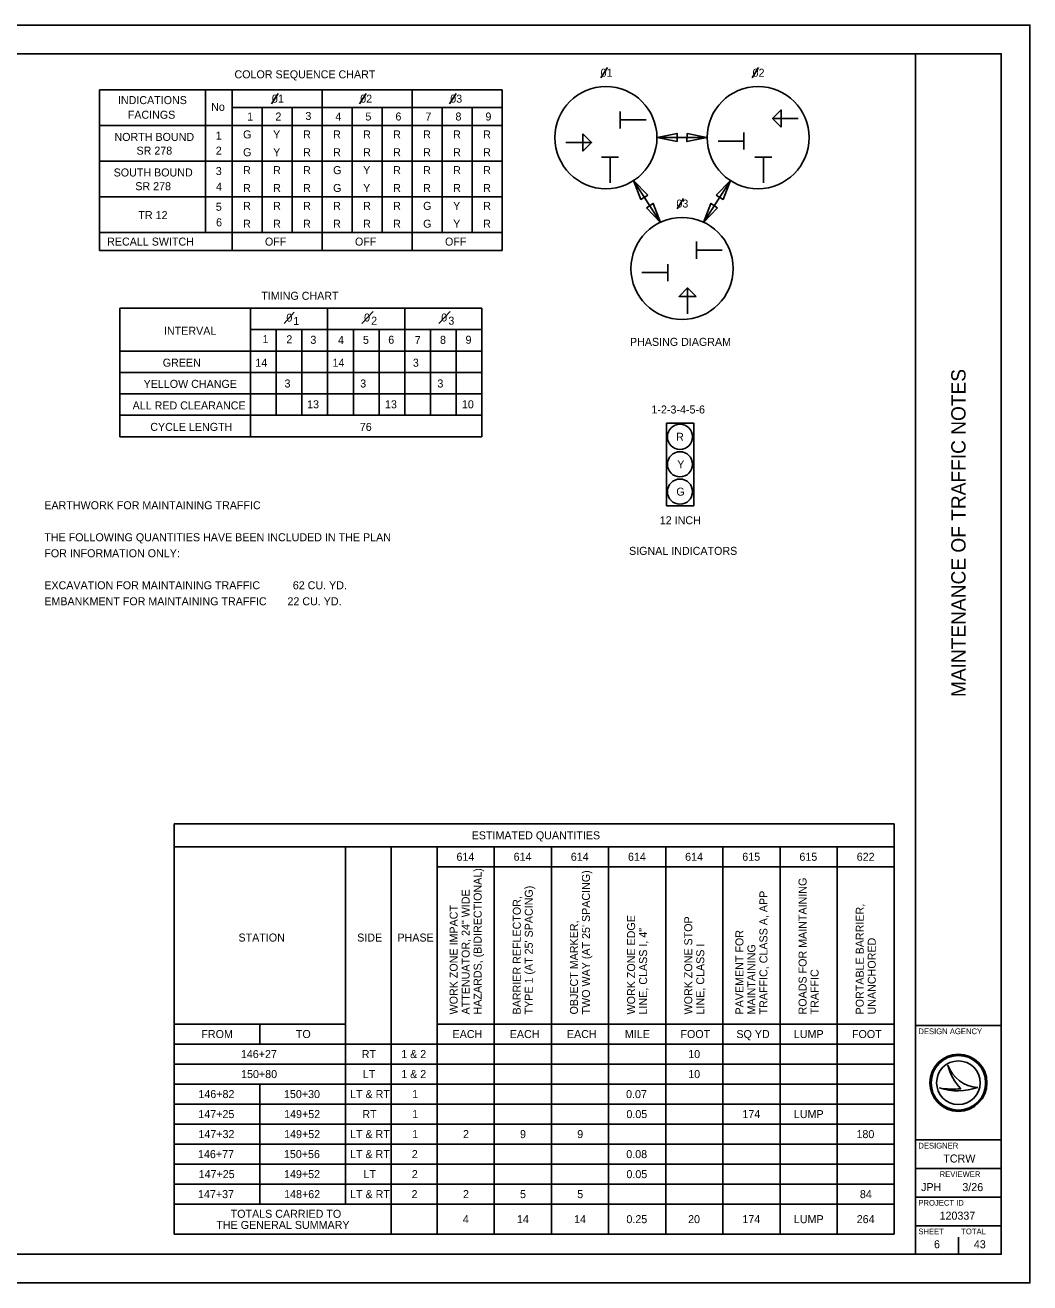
# Model space of a CAD drawing. Extents: x -39 to 34, y 0 to 22.
# Drawn here: x 16.42 to 34, y 0 to 22 of the extents above; entities that cross this region are included whole.
import ezdxf

# ---------------------------------------------------------------- set-up
doc = ezdxf.new("R2010")
doc.units = 0
for name, color, linetype in [('Default', 7, 'Continuous'), ('SG_P_Heads', 7, 'Continuous'), ('SH_Border', 7, 'Continuous'), ('SH_Cut_Line', 7, 'Continuous'), ('SH_Data', 7, 'Continuous'), ('SH_Text', 7, 'Continuous'), ('TX_P_1', 7, 'Continuous'), ('TX_P_20', 7, 'Continuous')]:
    doc.layers.add(name, color=color, linetype=linetype)

msp = doc.modelspace()

# ---------------------------------------------------------------- linework, layer by layer
at = {"layer": 'Default'}
for p, q in [((17.725, 20.871), (17.725, 18.059)), ((17.725, 20.871), (24.77, 20.871)), ((19.576, 20.871), (19.576, 18.371)), ((20.045, 20.871), (20.045, 18.059)), ((21.62, 20.871), (21.62, 18.059)), ((23.195, 20.871), (23.195, 18.684)), ((23.195, 20.871), (23.195, 18.059)), ((24.77, 20.871), (24.77, 18.059)), ((20.045, 20.559), (24.77, 20.559)), ((20.57, 20.559), (20.57, 18.371)), ((21.095, 20.559), (21.095, 18.371)), ((22.145, 20.559), (22.145, 18.371)), ((22.67, 20.559), (22.67, 18.371)), ((23.72, 20.559), (23.72, 18.371)), ((24.245, 20.559), (24.245, 18.371)), ((17.725, 20.246), (24.77, 20.246)), ((17.725, 19.621), (24.77, 19.621)), ((17.725, 18.996), (24.77, 18.996)), ((17.725, 18.371), (24.77, 18.371)), ((17.725, 18.059), (24.77, 18.059)), ((18.08, 17.05), (24.415, 17.05)), ((18.08, 17.05), (18.08, 14.8)), ((20.365, 17.05), (20.365, 14.8)), ((21.715, 17.05), (21.715, 15.175)), ((23.065, 17.05), (23.065, 15.175)), ((24.415, 17.05), (24.415, 14.8)), ((20.365, 16.675), (24.415, 16.675)), ((20.815, 16.675), (20.815, 15.175)), ((21.265, 16.675), (21.265, 15.175)), ((22.165, 16.675), (22.165, 15.175)), ((22.615, 16.675), (22.615, 15.175)), ((23.515, 16.675), (23.515, 15.175)), ((23.965, 16.675), (23.965, 15.175)), ((18.08, 16.3), (24.415, 16.3)), ((18.08, 15.925), (24.415, 15.925)), ((18.08, 15.55), (24.415, 15.55)), ((18.08, 15.175), (24.415, 15.175)), ((28.119, 15.036), (27.641, 15.036)), ((27.641, 15.036), (27.641, 13.594)), ((28.119, 13.594), (28.119, 15.036)), ((18.08, 14.8), (24.415, 14.8)), ((27.641, 13.594), (28.119, 13.594))]:
    msp.add_line(p, q, dxfattribs=at)
for centre in [(27.879, 14.799), (27.879, 14.319), (27.879, 13.84)]:
    msp.add_circle(centre, 0.22, dxfattribs=at)
at = {"layer": 'SG_P_Heads'}
for p, q in [((26.834, 20.491), (26.834, 20.191)), ((27.285, 20.341), (26.834, 20.341)), ((29.949, 20.367), (29.498, 20.367)), ((28.996, 19.823), (28.996, 20.123)), ((25.882, 19.947), (26.332, 19.947)), ((28.545, 19.973), (28.996, 19.973)), ((26.505, 19.693), (26.805, 19.693)), ((26.655, 19.242), (26.655, 19.693)), ((29.188, 19.693), (29.488, 19.693)), ((29.338, 19.242), (29.338, 19.693)), ((28.166, 18.215), (28.166, 17.915)), ((28.617, 18.065), (28.166, 18.065)), ((27.664, 17.521), (27.664, 17.821)), ((27.214, 17.671), (27.664, 17.671)), ((28.013, 16.953), (28.013, 17.404))]:
    msp.add_line(p, q, dxfattribs=at)
for points in [[(29.648, 20.217), (29.498, 20.367), (29.648, 20.517)], [(26.182, 20.097), (26.332, 19.947), (26.182, 19.797)], [(27.828, 19.965), (27.478, 20.037), (27.828, 20.105)], [(28.002, 20.104), (28.351, 20.032), (28.001, 19.964)], [(27.314, 19.027), (27.064, 19.282), (27.197, 18.951)], [(28.515, 19.027), (28.765, 19.282), (28.633, 18.951)], [(27.291, 18.805), (27.541, 18.55), (27.409, 18.882)], [(28.538, 18.805), (28.288, 18.55), (28.421, 18.882)], [(28.163, 17.254), (28.013, 17.404), (27.863, 17.254)]]:
    msp.add_lwpolyline(points, close=True, dxfattribs=at)
at = {"layer": 'SH_Border'}
for p, q in [((32, 0.5), (32, 21.5)), ((32, 4.5), (33.5, 4.5)), ((32, 2.5), (33.5, 2.5)), ((32, 2), (33.5, 2)), ((32, 1.5), (33.5, 1.5)), ((32, 1), (33.5, 1))]:
    msp.add_line(p, q, dxfattribs=at)
msp.add_lwpolyline([(1.5, 21.5), (33.5, 21.5), (33.5, 0.5), (1.5, 0.5)], close=True, dxfattribs=at)
at = {"layer": 'SH_Cut_Line'}
msp.add_lwpolyline([(0, 0), (34, 0), (34, 22), (0, 22)], close=True, dxfattribs=at)
at = {"layer": 'SH_Data'}
for p, q in [((28.351, 20.032), (27.478, 20.037)), ((27.541, 18.55), (27.064, 19.282)), ((28.288, 18.55), (28.765, 19.282)), ((32.567, 3.81), (32.567, 3.81)), ((32.417, 3.41), (32.417, 3.41)), ((32.75, 3.5), (32.75, 3.5)), ((33.087, 3.419), (33.087, 3.419)), ((32.375, 0.675), (32.375, 0.675)), ((32.75, 0.5), (32.75, 0.8))]:
    msp.add_line(p, q, dxfattribs=at)
for centre, radius in [((26.583, 20.032), 0.893), ((29.246, 20.032), 0.893), ((27.915, 17.743), 0.893), ((32.75, 3.5), 0.5), ((32.75, 3.5), 0.477), ((32.75, 3.5), 0.477), ((32.75, 3.5), 0.382)]:
    msp.add_circle(centre, radius, dxfattribs=at)
for centre, radius, start, end in [((33.116, 3.998), 0.58, 198.9257, 198.9319), ((33.347, 3.97), 0.796, 191.6379, 191.6421), ((33.116, 3.998), 0.58, 198.9319, 267.1657), ((33.347, 3.97), 0.796, 191.6421, 226.0947), ((32.739, 4.37), 1.013, 251.4576, 290.0832), ((32.648, 4.654), 1.266, 259.4964, 259.4995), ((32.739, 4.37), 1.013, 251.4527, 251.4576), ((32.648, 4.654), 1.266, 259.4995, 276.6672)]:
    msp.add_arc(centre, radius, start, end, dxfattribs=at)
at = {"layer": 'SH_Text'}
for p, q in [((19.029, 0.852), (19.029, 8.028)), ((19.029, 8.028), (31.629, 8.028)), ((31.629, 0.852), (31.629, 8.028)), ((19.029, 7.628), (31.629, 7.628)), ((22.029, 1.377), (22.029, 7.628)), ((22.829, 0.852), (22.829, 7.628)), ((23.629, 0.852), (23.629, 7.628)), ((24.629, 0.852), (24.629, 7.628)), ((25.629, 0.852), (25.629, 7.628)), ((26.629, 0.852), (26.629, 7.628)), ((27.629, 0.852), (27.629, 7.628)), ((28.629, 0.852), (28.629, 7.628)), ((29.629, 0.852), (29.629, 7.628)), ((30.629, 0.852), (30.629, 7.628)), ((23.629, 7.278), (31.629, 7.278)), ((19.029, 4.527), (22.029, 4.527)), ((20.529, 4.177), (20.529, 4.527)), ((23.629, 4.527), (31.629, 4.527)), ((19.029, 4.177), (31.629, 4.177)), ((19.029, 3.827), (31.629, 3.827)), ((19.029, 3.477), (31.629, 3.477)), ((20.529, 1.377), (20.529, 3.477)), ((19.029, 3.127), (31.629, 3.127)), ((19.029, 2.777), (31.629, 2.777)), ((19.029, 2.427), (31.629, 2.427)), ((19.029, 2.077), (31.629, 2.077)), ((19.029, 1.727), (31.629, 1.727)), ((19.029, 1.377), (31.629, 1.377)), ((19.029, 0.852), (31.629, 0.852))]:
    msp.add_line(p, q, dxfattribs=at)
at = {"layer": 'TX_P_1'}
for p, q in [((26.496, 21.077), (26.611, 21.258)), ((29.14, 21.077), (29.255, 21.258)), ((20.735, 20.624), (20.85, 20.805)), ((22.273, 20.624), (22.388, 20.805)), ((23.848, 20.624), (23.963, 20.805)), ((27.828, 18.788), (27.943, 18.969)), ((20.955, 16.781), (21.131, 16.981)), ((22.311, 16.782), (22.511, 16.991)), ((23.661, 16.782), (23.861, 16.991))]:
    msp.add_line(p, q, dxfattribs=at)

# ---------------------------------------------------------------- texts
at = {"layer": 'Default'}
for s, p in [('R', (27.811, 14.729)), ('Y', (27.831, 14.249)), ('G', (27.815, 13.77)), ('SIGNAL INDICATORS', (26.988, 12.734))]:
    msp.add_text(s, height=0.14, dxfattribs=at).set_placement(p)
at = {"layer": 'SH_Data'}
msp.add_text('MAINTENANCE OF TRAFFIC NOTES', height=0.25, rotation=90, dxfattribs=at).set_placement((32.875, 10.247))
for s, height, p in [('DESIGN AGENCY', 0.1, (32.05, 4.35)), ('DESIGNER', 0.1, (32.05, 2.35)), ('TCRW', 0.14, (32.486, 2.105)), ('REVIEWER', 0.1, (32.422, 1.85)), ('JPH', 0.14, (32.098, 1.605)), ('3/26', 0.14, (32.819, 1.605)), ('PROJECT ID', 0.1, (32.05, 1.35)), ('120337', 0.14, (32.42, 1.105)), ('SHEET', 0.1, (32.05, 0.85)), ('TOTAL', 0.1, (32.8, 0.85)), ('6', 0.14, (32.323, 0.605)), ('43', 0.14, (33.02, 0.605))]:
    msp.add_text(s, height=height, dxfattribs=at).set_placement(p)
at = {"layer": 'SH_Text'}
for s, p in [('COLOR SEQUENCE CHART', (20.085, 21.07)), ('TIMING CHART', (20.554, 17.196)), ('EARTHWORK FOR MAINTAINING TRAFFIC', (16.758, 13.532)), ('THE FOLLOWING QUANTITIES HAVE BEEN INCLUDED IN THE PLAN', (16.758, 12.972)), ('FOR INFORMATION ONLY:', (16.758, 12.692)), ('EXCAVATION FOR MAINTAINING TRAFFIC           62 CU. YD.', (16.758, 12.132)), ('EMBANKMENT FOR MAINTAINING TRAFFIC       22 CU. YD.', (16.758, 11.852)), ('ESTIMATED QUANTITIES', (24.235, 7.758)), ('614', (23.969, 7.383)), ('614', (24.969, 7.383)), ('614', (25.969, 7.383)), ('614', (26.969, 7.383)), ('614', (27.969, 7.383)), ('615', (28.969, 7.383)), ('615', (29.969, 7.383)), ('622', (30.971, 7.383)), ('STATION', (20.155, 5.97)), ('SIDE', (22.232, 5.97)), ('PHASE', (22.936, 5.97)), ('FROM', (19.506, 4.282)), ('TO', (21.159, 4.282)), ('EACH', (23.901, 4.282)), ('EACH', (24.901, 4.282)), ('EACH', (25.901, 4.282)), ('MILE', (26.915, 4.282)), ('FOOT', (27.888, 4.282)), ('SQ YD', (28.866, 4.282)), ('LUMP', (29.872, 4.282)), ('FOOT', (30.888, 4.282)), ('146+27', (20.197, 3.932)), ('RT', (22.311, 3.932)), ('1 & 2', (23.002, 3.932)), ('10', (28.023, 3.932)), ('150+80', (20.201, 3.582)), ('LT', (22.33, 3.582)), ('1 & 2', (23.002, 3.582)), ('10', (28.023, 3.582)), ('146+82', (19.454, 3.232)), ('150+30', (20.951, 3.232)), ('LT & RT', (22.107, 3.232)), ('1', (23.194, 3.232)), ('0.07', (26.936, 3.232)), ('147+25', (19.453, 2.882)), ('149+52', (20.954, 2.882)), ('RT', (22.322, 2.882)), ('1', (23.194, 2.882)), ('0.05', (26.942, 2.882)), ('174', (28.971, 2.882)), ('LUMP', (29.872, 2.882)), ('147+32', (19.454, 2.532)), ('149+52', (20.954, 2.532)), ('LT & RT', (22.106, 2.532)), ('1', (23.194, 2.532)), ('2', (24.083, 2.532)), ('9', (25.081, 2.532)), ('9', (26.081, 2.532)), ('180', (30.967, 2.532)), ('146+77', (19.447, 2.182)), ('150+56', (20.95, 2.182)), ('LT & RT', (22.106, 2.182)), ('2', (23.187, 2.182)), ('0.08', (26.94, 2.182)), ('147+25', (19.458, 1.832)), ('149+52', (20.952, 1.832)), ('LT', (22.343, 1.832)), ('2', (23.187, 1.832)), ('0.05', (26.942, 1.832)), ('147+37', (19.447, 1.482)), ('148+62', (20.954, 1.482)), ('LT & RT', (22.107, 1.482)), ('2', (23.183, 1.482)), ('2', (24.083, 1.482)), ('5', (25.081, 1.482)), ('5', (26.081, 1.482)), ('84', (31.027, 1.482)), ('TOTALS CARRIED TO', (20.018, 1.138)), ('4', (24.081, 1.044)), ('14', (25.027, 1.044)), ('14', (26.027, 1.044)), ('0.25', (26.942, 1.044)), ('20', (28.021, 1.044)), ('174', (28.971, 1.044)), ('LUMP', (29.872, 1.044)), ('264', (30.971, 1.044)), ('THE GENERAL SUMMARY', (19.768, 0.943))]:
    msp.add_text(s, height=0.14, dxfattribs=at).set_placement(p)
for s, p in [('HAZARDS, (BIDIRECTIONAL)', (24.409, 4.695)), ("TWO WAY (AT 25' SPACING)", (26.304, 4.695)), ('ROADS FOR MAINTAINING', (30.094, 4.695)), ('ATTENUATOR, 24" WIDE', (24.199, 4.695)), ("TYPE 1 (AT 25' SPACING)", (25.304, 4.695)), ('TRAFFIC, CLASS A, APP', (29.409, 4.695)), ('WORK ZONE IMPACT', (23.989, 4.695)), ('BARRIER REFLECTOR,', (25.094, 4.695)), ('PORTABLE BARRIER,', (31.094, 4.695)), ('WORK ZONE EDGE', (27.094, 4.695)), ('WORK ZONE STOP', (28.094, 4.695)), ('OBJECT MARKER,', (26.094, 4.695)), ('LINE, CLASS I, 4"', (27.304, 4.695)), ('PAVEMENT FOR', (28.989, 4.695)), ('UNANCHORED', (31.304, 4.695)), ('LINE, CLASS I', (28.304, 4.695)), ('MAINTAINING', (29.199, 4.695)), ('TRAFFIC', (30.304, 4.695))]:
    msp.add_text(s, height=0.14, rotation=90, dxfattribs=at).set_placement(p)
at = {"layer": 'TX_P_1'}
for s, p in [('INDICATIONS', (18.046, 20.619)), ('01', (20.74, 20.644)), ('02', (22.285, 20.644)), ('03', (23.86, 20.644)), ('FACINGS', (18.218, 20.363)), ('No', (19.677, 20.501)), ('1', (20.307, 20.332)), ('2', (20.801, 20.332)), ('3', (21.326, 20.342)), ('4', (21.851, 20.332)), ('5', (22.376, 20.332)), ('6', (22.901, 20.332)), ('7', (23.426, 20.332)), ('8', (23.951, 20.332)), ('9', (24.476, 20.332)), ('NORTH BOUND', (17.985, 19.975)), ('1', (19.758, 19.999)), ('G', (20.236, 20.019)), ('Y', (20.761, 20.019)), ('R', (21.286, 20.019)), ('R', (21.811, 20.019)), ('R', (22.336, 20.019)), ('R', (22.861, 20.019)), ('R', (23.386, 20.019)), ('R', (23.911, 20.019)), ('R', (24.436, 20.019)), ('SR 278', (18.371, 19.735)), ('2', (19.758, 19.735)), ('G', (20.236, 19.707)), ('Y', (20.761, 19.707)), ('R', (21.286, 19.707)), ('R', (21.811, 19.707)), ('R', (22.336, 19.707)), ('R', (22.861, 19.707)), ('R', (23.386, 19.707)), ('R', (23.911, 19.707)), ('R', (24.436, 19.707)), ('SOUTH BOUND', (17.971, 19.353)), ('3', (19.758, 19.378)), ('R', (20.236, 19.394)), ('R', (20.761, 19.394)), ('R', (21.286, 19.394)), ('G', (21.811, 19.394)), ('Y', (22.336, 19.394)), ('R', (22.861, 19.394)), ('R', (23.386, 19.394)), ('R', (23.911, 19.394)), ('R', (24.436, 19.394)), ('SR 278', (18.35, 19.113)), ('4', (19.763, 19.106)), ('R', (20.236, 19.082)), ('R', (20.761, 19.082)), ('R', (21.286, 19.082)), ('G', (21.811, 19.082)), ('Y', (22.336, 19.082)), ('R', (22.861, 19.082)), ('R', (23.386, 19.082)), ('R', (23.911, 19.082)), ('R', (24.436, 19.082)), ('TR 12', (18.404, 18.608)), ('5', (19.758, 18.753)), ('R', (20.236, 18.769)), ('R', (20.761, 18.769)), ('R', (21.286, 18.769)), ('R', (21.811, 18.769)), ('R', (22.336, 18.769)), ('R', (22.861, 18.769)), ('G', (23.386, 18.769)), ('Y', (23.911, 18.769)), ('R', (24.436, 18.769)), ('6', (19.763, 18.481)), ('R', (20.236, 18.457)), ('R', (20.761, 18.457)), ('R', (21.286, 18.457)), ('R', (21.811, 18.457)), ('R', (22.336, 18.457)), ('R', (22.861, 18.457)), ('G', (23.386, 18.457)), ('Y', (23.911, 18.457)), ('R', (24.436, 18.457)), ('RECALL SWITCH', (17.857, 18.144)), ('OFF', (20.618, 18.144)), ('OFF', (22.193, 18.144)), ('OFF', (23.768, 18.144)), ('0', (20.993, 16.813)), ('0', (22.352, 16.816)), ('0', (23.702, 16.816)), ('INTERVAL ', (18.852, 16.584)), ('1', (21.115, 16.757)), ('2', (22.477, 16.76)), ('3', (23.827, 16.76)), ('1', (20.575, 16.438)), ('2', (20.992, 16.436)), ('3', (21.413, 16.426)), ('4', (21.895, 16.422)), ('5', (22.333, 16.425)), ('6', (22.775, 16.427)), ('7', (23.238, 16.422)), ('8', (23.681, 16.425)), ('9', (24.127, 16.427)), ('PHASING DIAGRAM', (27.004, 16.39)), (' GREEN', (18.778, 16.026)), ('14', (20.45, 16.025)), ('14', (21.8, 16.025)), ('3', (23.206, 16.025)), ('YELLOW CHANGE', (18.495, 15.655)), ('3', (20.961, 15.662)), ('3', (22.285, 15.662)), ('3', (23.635, 15.662)), ('ALL RED CLEARANCE', (18.303, 15.278)), ('13', (21.356, 15.298)), ('13', (22.718, 15.298)), ('10', (24.064, 15.298)), ('1-2-3-4-5-6', (27.38, 15.207)), ('CYCLE LENGTH', (18.612, 14.903)), ('76', (22.278, 14.902)), ('12 INCH', (27.526, 13.269))]:
    msp.add_text(s, height=0.14, dxfattribs=at).set_placement(p)
at = {"layer": 'TX_P_20'}
for s, p in [('01', (26.491, 21.098)), ('02', (29.15, 21.098)), ('03', (27.817, 18.809))]:
    msp.add_text(s, height=0.14, dxfattribs=at).set_placement(p)

doc.saveas('drawing.dxf')
